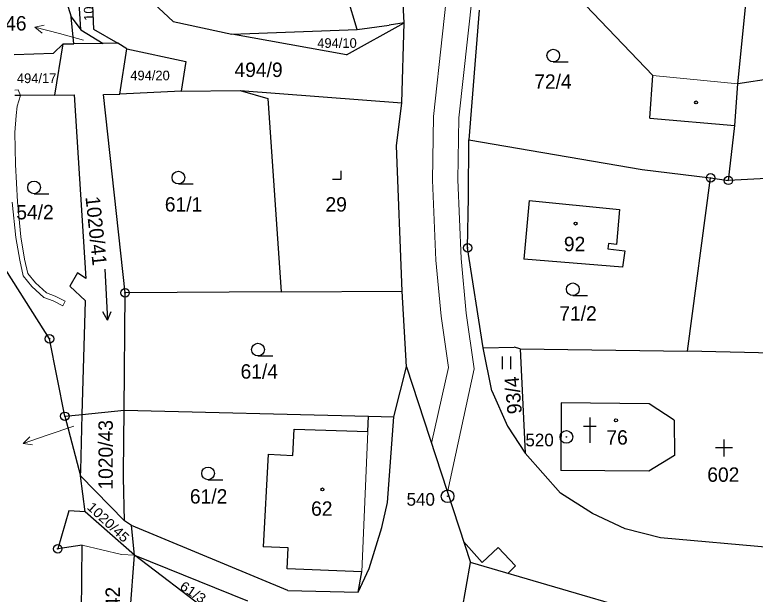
# Model space of a CAD drawing. Extents: x -601131 to -597152, y -1058536 to -1055911.
# Drawn here: x -599468.7 to -599381.2, y -1057123.5 to -1057055.1 of the extents above; entities that cross this region are included whole.
import ezdxf
from ezdxf.enums import TextEntityAlignment as Align

# ---------------------------------------------------------------- set-up
doc = ezdxf.new("R2010")
doc.units = 0
doc.header["$LTSCALE"] = 0.68
for name, color, linetype, lineweight in [('1', 7, 'Continuous', 25), ('13', 7, 'Continuous', 13), ('3', 7, 'Continuous', 25), ('4', 7, 'Continuous', 13), ('5', 7, 'Continuous', 25), ('7', 7, 'Continuous', 13), ('8', 7, 'Continuous', 25)]:
    doc.layers.add(name, color=color, linetype=linetype, lineweight=lineweight)
doc.layers.add('2', color=7, linetype='Continuous')

msp = doc.modelspace()

# ---------------------------------------------------------------- linework, layer by layer
at = {"layer": '1'}
for p, q in [((-599428.27, -1057056.8), (-599437.5, -1057025.97)), ((-599460.91, -1057056.82), (-599461.88, -1057041.02)), ((-599393.36, -1057062.2), (-599405.37, -1057049.65)), ((-599463.71, -1057050), (-599462.05, -1057055.3)), ((-599459.69, -1057050.12), (-599459.42, -1057056.74)), ((-599383.28, -1057063.21), (-599382.18, -1057052.14)), ((-599422.72, -1057056), (-599422.91, -1057052.37)), ((-599450.01, -1057055.83), (-599452.28, -1057053.7)), ((-599413.85, -1057054.49), (-599415.07, -1057069.81)), ((-599461.77, -1057058.48), (-599462.05, -1057055.3)), ((-599462.05, -1057055.3), (-599460.91, -1057056.82)), ((-599450.01, -1057055.83), (-599443.08, -1057057.33)), ((-599429.52, -1057059.77), (-599422.72, -1057056)), ((-599428.27, -1057056.8), (-599424.5, -1057056.28)), ((-599422.72, -1057056), (-599424.5, -1057056.28)), ((-599423.01, -1057065.45), (-599422.72, -1057056)), ((-599460.91, -1057056.82), (-599458.3, -1057058.44)), ((-599459.42, -1057056.74), (-599456.56, -1057058.42)), ((-599443.08, -1057057.33), (-599428.27, -1057056.8)), ((-599429.52, -1057059.77), (-599443.08, -1057057.33)), ((-599458.3, -1057058.44), (-599461.77, -1057058.48)), ((-599456.56, -1057058.42), (-599458.3, -1057058.44)), ((-599455.49, -1057059.05), (-599456.56, -1057058.42)), ((-599464.17, -1057059.6), (-599463.03, -1057058.49)), ((-599464, -1057064.55), (-599463.03, -1057058.49)), ((-599463.03, -1057058.49), (-599461.77, -1057058.48)), ((-599456.3, -1057064.44), (-599455.49, -1057059.05)), ((-599455.49, -1057059.05), (-599448.52, -1057060.56)), ((-599468.81, -1057059.73), (-599464.17, -1057059.6)), ((-599448.52, -1057060.56), (-599449.06, -1057064.08)), ((-599371.54, -1057061.4), (-599383.28, -1057063.21)), ((-599393.69, -1057067.27), (-599393.36, -1057062.2)), ((-599383.66, -1057068.13), (-599383.28, -1057063.21)), ((-599464, -1057064.55), (-599468.73, -1057064.59)), ((-599464, -1057064.55), (-599461.73, -1057064.52)), ((-599461.73, -1057064.52), (-599460.32, -1057086.2)), ((-599458.24, -1057064.47), (-599456.3, -1057064.44)), ((-599455.7, -1057087.88), (-599458.24, -1057064.47)), ((-599449.06, -1057064.08), (-599456.3, -1057064.44)), ((-599449.06, -1057064.08), (-599442.09, -1057063.98)), ((-599442.09, -1057063.98), (-599423.01, -1057065.45)), ((-599442.09, -1057063.98), (-599438.84, -1057064.92)), ((-599438.84, -1057064.92), (-599437.24, -1057087.75)), ((-599423.61, -1057070.52), (-599423.01, -1057065.45)), ((-599393.69, -1057067.27), (-599383.66, -1057068.13)), ((-599384.42, -1057074.6), (-599383.66, -1057068.13)), ((-599415.14, -1057076.6), (-599415.07, -1057069.81)), ((-599415.07, -1057069.81), (-599394.62, -1057073.31)), ((-599422.96, -1057087.68), (-599423.61, -1057070.52)), ((-599394.62, -1057073.31), (-599386.52, -1057074.31)), ((-599359.44, -1057073.38), (-599384.42, -1057074.6)), ((-599389.23, -1057094.77), (-599386.52, -1057074.31)), ((-599386.52, -1057074.31), (-599384.42, -1057074.6)), ((-599415.22, -1057082.57), (-599415.14, -1057076.6)), ((-599407.94, -1057076.96), (-599408.58, -1057083.89)), ((-599407.94, -1057076.96), (-599397.28, -1057078.04)), ((-599397.28, -1057078.04), (-599397.64, -1057082.17)), ((-599398.57, -1057082.07), (-599398.64, -1057082.7)), ((-599397.64, -1057082.17), (-599398.57, -1057082.07)), ((-599413.38, -1057094.37), (-599415.22, -1057082.57)), ((-599398.64, -1057082.7), (-599396.64, -1057082.92)), ((-599396.64, -1057082.92), (-599396.92, -1057084.86)), ((-599464.62, -1057093.31), (-599470.35, -1057084.3)), ((-599396.92, -1057084.86), (-599408.58, -1057083.89)), ((-599461.3, -1057085.51), (-599462.24, -1057087.11)), ((-599460.32, -1057086.2), (-599461.3, -1057085.51)), ((-599462.24, -1057087.11), (-599460.39, -1057088.84)), ((-599455.8, -1057101.73), (-599455.7, -1057087.88)), ((-599437.24, -1057087.75), (-599455.7, -1057087.88)), ((-599437.24, -1057087.75), (-599422.96, -1057087.68)), ((-599422.45, -1057096.63), (-599422.96, -1057087.68)), ((-599460.76, -1057102.25), (-599460.39, -1057088.84)), ((-599462.81, -1057102.46), (-599464.62, -1057093.31)), ((-599413.38, -1057094.37), (-599409.74, -1057094.31)), ((-599409, -1057094.48), (-599409.74, -1057094.31)), ((-599412.37, -1057099.47), (-599413.38, -1057094.37)), ((-599409, -1057094.48), (-599408.42, -1057106.8)), ((-599409, -1057094.48), (-599389.23, -1057094.77)), ((-599375.11, -1057095.12), (-599389.23, -1057094.77)), ((-599423.93, -1057102.54), (-599422.45, -1057096.63)), ((-599422.45, -1057096.63), (-599414.88, -1057119.74)), ((-599412.37, -1057099.47), (-599410.53, -1057103.61)), ((-599404.18, -1057100.88), (-599404.22, -1057108.86)), ((-599393.76, -1057100.97), (-599404.18, -1057100.88)), ((-599390.81, -1057102.91), (-599393.76, -1057100.97)), ((-599460.76, -1057102.25), (-599455.8, -1057101.73)), ((-599455.9, -1057109.1), (-599455.8, -1057101.73)), ((-599455.8, -1057101.73), (-599426.93, -1057102.46)), ((-599462.81, -1057102.46), (-599460.76, -1057102.25)), ((-599462.81, -1057102.46), (-599460.95, -1057109.48)), ((-599460.94, -1057108.85), (-599460.76, -1057102.25)), ((-599427.01, -1057104.27), (-599426.93, -1057102.46)), ((-599426.93, -1057102.46), (-599423.93, -1057102.54)), ((-599424.71, -1057112.64), (-599423.93, -1057102.54)), ((-599390.81, -1057102.91), (-599390.8, -1057107.08)), ((-599435.87, -1057107.07), (-599435.7, -1057103.96)), ((-599435.7, -1057103.96), (-599427.01, -1057104.27)), ((-599410.53, -1057103.61), (-599408.42, -1057106.8)), ((-599438.78, -1057106.92), (-599439.39, -1057117.88)), ((-599438.78, -1057106.92), (-599435.87, -1057107.07)), ((-599404.25, -1057111.55), (-599408.42, -1057106.8)), ((-599390.8, -1057107.08), (-599393.81, -1057108.95)), ((-599460.95, -1057109.48), (-599460.94, -1057108.85)), ((-599455.89, -1057109.68), (-599455.9, -1057109.1)), ((-599393.81, -1057108.95), (-599404.22, -1057108.86)), ((-599460.42, -1057113.75), (-599460.95, -1057109.48)), ((-599455.76, -1057114.82), (-599460.95, -1057109.48)), ((-599455.76, -1057114.82), (-599455.89, -1057109.68)), ((-599400.48, -1057113.94), (-599404.25, -1057111.55)), ((-599425.36, -1057115.59), (-599424.71, -1057112.64)), ((-599462.34, -1057113.64), (-599463.65, -1057118.11)), ((-599460.42, -1057113.75), (-599462.34, -1057113.64)), ((-599454.57, -1057118.86), (-599460.42, -1057113.75)), ((-599396.61, -1057115.73), (-599400.48, -1057113.94)), ((-599454.93, -1057115.35), (-599455.76, -1057114.82)), ((-599454.57, -1057118.86), (-599454.93, -1057115.35)), ((-599436.46, -1057123.03), (-599454.93, -1057115.35)), ((-599426.86, -1057120.43), (-599425.36, -1057115.59)), ((-599392.44, -1057116.83), (-599396.61, -1057115.73)), ((-599370.11, -1057118.82), (-599392.44, -1057116.83)), ((-599460.76, -1057117.69), (-599463.65, -1057118.11)), ((-599461.04, -1057148.74), (-599460.76, -1057117.69)), ((-599436.44, -1057118.01), (-599439.39, -1057117.88)), ((-599436.55, -1057120.47), (-599436.44, -1057118.01)), ((-599456.32, -1057140.87), (-599454.57, -1057118.86)), ((-599444.88, -1057126.24), (-599454.57, -1057118.86)), ((-599454.57, -1057118.86), (-599441.23, -1057124.24)), ((-599427.73, -1057120.83), (-599436.55, -1057120.47)), ((-599428.15, -1057123.22), (-599426.86, -1057120.43)), ((-599415.94, -1057125.73), (-599414.88, -1057119.74)), ((-599392.5, -1057126.24), (-599414.88, -1057119.74)), ((-599428.15, -1057123.22), (-599427.73, -1057120.83)), ((-599436.46, -1057123.03), (-599428.15, -1057123.22))]:
    msp.add_line(p, q, dxfattribs=at)
at = {"layer": '13'}
for points in [[(-599417.11, -1057047.5), (-599419.27, -1057067.05), (-599419.39, -1057074.59), (-599418.97, -1057084.02), (-599418.36, -1057090.64), (-599417.48, -1057096.71), (-599419.5, -1057105.63), (-599417.61, -1057111.4), (-599414.44, -1057096.84), (-599415.38, -1057090.27), (-599415.98, -1057083.82), (-599416.39, -1057074.55), (-599416.28, -1057067.22), (-599414.13, -1057047.91)], [(-599469.02, -1057077.16), (-599468.62, -1057081.36), (-599468.15, -1057084.04), (-599467.75, -1057085.89), (-599466.71, -1057087.14), (-599465.29, -1057088.42), (-599464.2, -1057088.83), (-599463.04, -1057089.41), (-599462.77, -1057088.88), (-599463.96, -1057088.27), (-599464.97, -1057087.9), (-599466.27, -1057086.72), (-599467.19, -1057085.61), (-599467.57, -1057083.92), (-599468.02, -1057081.28), (-599468.42, -1057077.12), (-599468.64, -1057072.74), (-599468.72, -1057068.94), (-599468.57, -1057066.96), (-599468.44, -1057065.82), (-599468.07, -1057064.58), (-599468.73, -1057064.59)], [(-599468.73, -1057064.59), (-599468.07, -1057064.58), (-599468.34, -1057063.93), (-599468.74, -1057063.94)]]:
    msp.add_lwpolyline(points, dxfattribs=at)
msp.add_lwpolyline([(-599415.7, -1057117.24), (-599414.88, -1057119.74), (-599410.49, -1057121.01), (-599409.55, -1057120.13), (-599411.61, -1057117.95), (-599413.49, -1057119.73)], close=True, dxfattribs=at)
at = {"layer": '3'}
for p, q in [((-599405.113, -1057060.61), (-599403.363, -1057060.61)), ((-599449.393, -1057075.02), (-599447.643, -1057075.02)), ((-599466.453, -1057076.18), (-599464.703, -1057076.18)), ((-599402.793, -1057088.21), (-599401.043, -1057088.21)), ((-599457.771, -1057091.093), (-599458.323, -1057090.144)), ((-599439.993, -1057095.33), (-599438.243, -1057095.33)), ((-599411.111, -1057096.9), (-599411.111, -1057095.4)), ((-599410.11, -1057096.9), (-599410.11, -1057095.4)), ((-599384.92, -1057107.2), (-599384.92, -1057105.2)), ((-599383.919, -1057106.201), (-599385.921, -1057106.201)), ((-599445.883, -1057109.96), (-599444.133, -1057109.96))]:
    msp.add_line(p, q, dxfattribs=at)
for points in [[(-599431.171, -1057074.46), (-599430.17, -1057074.46), (-599430.17, -1057073.46)], [(-599458.085, -1057085.102), (-599457.771, -1057091.093), (-599457.321, -1057090.091)]]:
    msp.add_lwpolyline(points, dxfattribs=at)
for centre in [(-599405.1129, -1057059.8598), (-599449.3929, -1057074.2698), (-599466.4529, -1057075.4298), (-599402.7929, -1057087.4598), (-599439.9929, -1057094.5798), (-599445.8829, -1057109.2098)]:
    msp.add_circle(centre, 0.75, dxfattribs=at)
at = {"layer": '4'}
for p, q in [((-599393.36, -1057062.2), (-599383.28, -1057063.21)), ((-599427.73, -1057120.83), (-599427.01, -1057104.27)), ((-599456.11, -1057118.79), (-599460.76, -1057117.69)), ((-599456.11, -1057118.79), (-599454.57, -1057118.86))]:
    msp.add_line(p, q, dxfattribs=at)
at = {"layer": '5'}
for p, q in [((-599400.77, -1057102.61), (-599400.77, -1057105.61)), ((-599401.521, -1057103.611), (-599400.019, -1057103.611))]:
    msp.add_line(p, q, dxfattribs=at)
for centre in [(-599388.2268, -1057065.3992), (-599402.4668, -1057079.6992), (-599397.6968, -1057102.9392), (-599432.3768, -1057111.0992)]:
    msp.add_circle(centre, 0.175, dxfattribs=at)
at = {"layer": '7'}
for p, q in [((-599466.349, -1057056.493), (-599465.511, -1057057.236)), ((-599467.747, -1057105.667), (-599466.638, -1057105.814))]:
    msp.add_line(p, q, dxfattribs=at)
for points in [[(-599460.59, -1057058.05), (-599463.45, -1057057.27), (-599466.349, -1057056.493), (-599465.252, -1057056.269)], [(-599461.76, -1057103.62), (-599464.91, -1057104.69), (-599467.747, -1057105.667), (-599466.964, -1057104.868)]]:
    msp.add_lwpolyline(points, dxfattribs=at)
at = {"layer": '8'}
for centre, radius in [((-599386.52, -1057074.3099), 0.5), ((-599384.42, -1057074.5999), 0.5), ((-599386.52, -1057074.3099), 0.0303), ((-599384.42, -1057074.5999), 0.0303), ((-599415.22, -1057082.5699), 0.5), ((-599415.22, -1057082.5699), 0.0303), ((-599455.7, -1057087.8799), 0.5), ((-599455.7, -1057087.8799), 0.0303), ((-599464.62, -1057093.3099), 0.5), ((-599464.62, -1057093.3099), 0.0303), ((-599462.81, -1057102.4599), 0.5), ((-599462.81, -1057102.4599), 0.0303), ((-599403.55, -1057104.8898), 0.75), ((-599403.55, -1057104.8898), 0.03), ((-599417.59, -1057111.8998), 0.75), ((-599417.59, -1057111.8998), 0.03), ((-599463.65, -1057118.1099), 0.5), ((-599463.65, -1057118.1099), 0.0303)]:
    msp.add_circle(centre, radius, dxfattribs=at)

# ---------------------------------------------------------------- texts
at = {"layer": '2'}
for s, height, rotation, p in [('1020/4', 1.14, 91, (-599459.405, -1057055.755)), ('1020/41', 1.7, 276, (-599460.382, -1057076.564)), ('93/4', 1.7, 95, (-599408.806, -1057102.122)), ('1020/43', 1.7, 90, (-599457.145, -1057111.12)), ('1020/42', 1.7, 91, (-599456.175, -1057130.802))]:
    msp.add_text(s, height=height, rotation=rotation, dxfattribs=at).set_placement(p)
msp.add_text('1020/46', height=1.7, dxfattribs=at).set_placement((-599467.34, -1057056.905), align=Align.RIGHT)
for s, height, p in [('494/10', 1.14, (-599432.99, -1057058.954)), ('494/9', 1.7, (-599442.77, -1057062.395)), ('494/17', 1.14, (-599468.48, -1057063.115)), ('494/20', 1.14, (-599455.08, -1057062.785)), ('72/4', 1.7, (-599407.35, -1057063.785)), ('61/1', 1.7, (-599451, -1057078.285)), ('29', 1.7, (-599432.02, -1057078.285)), ('54/2', 1.7, (-599468.55, -1057079.205)), ('92', 1.7, (-599403.85, -1057082.965)), ('71/2', 1.7, (-599404.39, -1057091.165)), ('61/4', 1.7, (-599442.05, -1057098.015)), ('76', 1.7, (-599398.83, -1057105.804)), ('602', 1.7, (-599386.91, -1057110.195)), ('61/2', 1.7, (-599448.04, -1057112.765)), ('62', 1.7, (-599433.72, -1057114.205))]:
    msp.add_text(s, height=height, dxfattribs=at).set_placement(p)
at = {"layer": '2', "width": 1.1}
for s, rotation, p in [('1020/45', 317, (-599460.284, -1057113.308)), ('61/3', 326, (-599449.339, -1057122.796))]:
    msp.add_text(s, height=1.14, rotation=rotation, dxfattribs=at).set_placement(p)
at = {"layer": '8'}
for s, p in [('520', (-599405.049, -1057106.007)), ('540', (-599419.089, -1057113.017))]:
    msp.add_text(s, height=1.5, dxfattribs=at).set_placement(p, align=Align.RIGHT)

doc.saveas('drawing.dxf')
